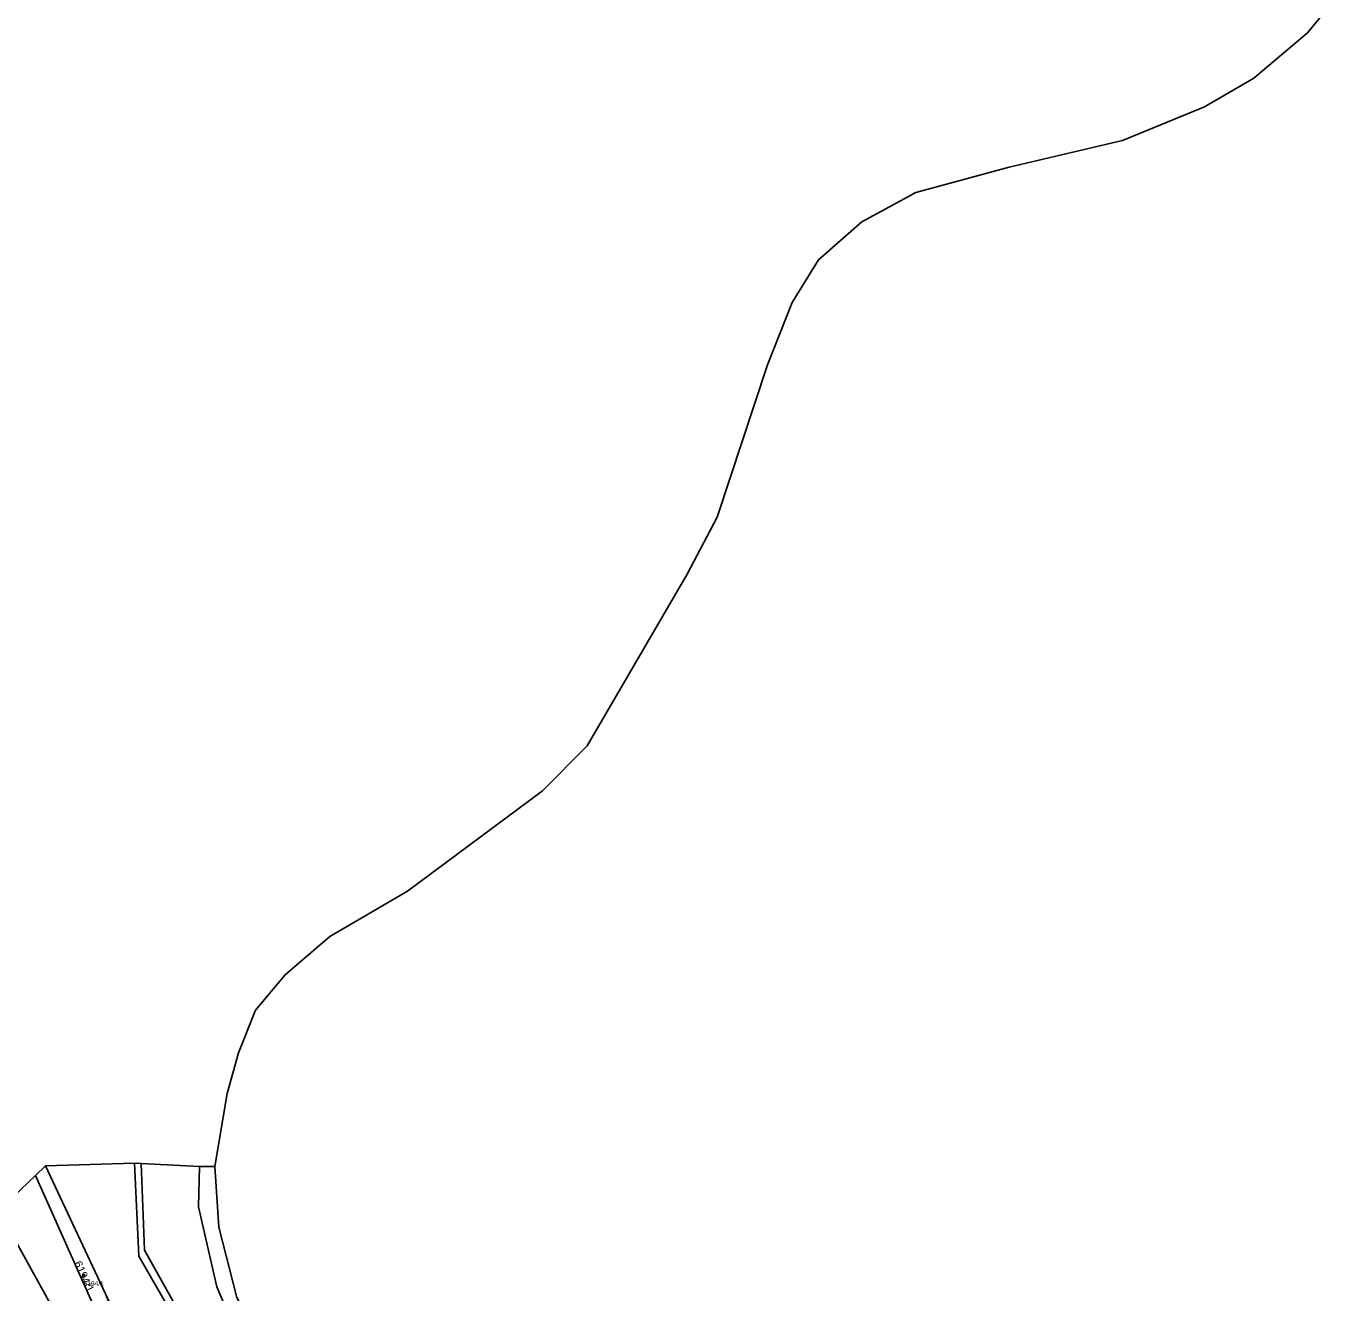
# Model space of a CAD drawing. Extents: x -754150 to -749824, y -1058608 to -1053956.
# Drawn here: x -753501.7 to -753222.7, y -1055960.5 to -1055691.3 of the extents above; entities that cross this region are included whole.
import ezdxf

# ---------------------------------------------------------------- set-up
doc = ezdxf.new("R2010")
doc.units = 0
for name, color, linetype in [('Vrstva 1', 7, 'Continuous'), ('Vrstva 2', 7, 'Continuous'), ('Vrstva 50', 7, 'Continuous'), ('Vrstva 51', 7, 'Continuous'), ('Vrstva 53', 7, 'Continuous')]:
    doc.layers.add(name, color=color, linetype=linetype)

msp = doc.modelspace()

# ---------------------------------------------------------------- linework, layer by layer
at = {"layer": 'Vrstva 1'}
for p, q in [((-753354.9, -1055795.67), (-753344.24, -1055763.29)), ((-753361.32, -1055807.74), (-753354.9, -1055795.67)), ((-753382.57, -1055844.21), (-753361.32, -1055807.74)), ((-753392.04, -1055853.78), (-753382.57, -1055844.21)), ((-753420.74, -1055875.1), (-753392.04, -1055853.78)), ((-753497.62, -1055933.49), (-753478.72, -1055932.93)), ((-753478.72, -1055932.93), (-753477.31, -1055932.99)), ((-753477.31, -1055932.99), (-753464.9, -1055933.61)), ((-753507.59, -1055943.01), (-753499.79, -1055935.57)), ((-753499.79, -1055935.57), (-753497.62, -1055933.49)), ((-753497.62, -1055933.49), (-753484.98, -1055960.55)), ((-753464.9, -1055933.61), (-753461.69, -1055933.61))]:
    msp.add_line(p, q, dxfattribs=at)
for points in [[(-753344.24, -1055763.29), (-753339.02, -1055750.02), (-753333.4, -1055740.97), (-753324.16, -1055732.93), (-753312.73, -1055726.7), (-753292.87, -1055721.27), (-753268.8, -1055715.65), (-753251.37, -1055708.45), (-753240.91, -1055702.38), (-753229.47, -1055692.73), (-753222.65, -1055684.29)], [(-753461.69, -1055933.61), (-753459.07, -1055918.12), (-753456.6, -1055909.51), (-753453.01, -1055900.39), (-753446.73, -1055892.88), (-753437.24, -1055884.79), (-753420.74, -1055875.1)], [(-753478.72, -1055932.93), (-753477.78, -1055952.7), (-753457.37, -1055988.27), (-753443.25, -1056005.88), (-753396.93, -1056060.7), (-753389.99, -1056071.74)], [(-753477.31, -1055932.99), (-753476.58, -1055951.4), (-753456.25, -1055987.76), (-753395.56, -1056059.9)], [(-753499.79, -1055935.57), (-753484, -1055970.96), (-753469.65, -1055999.21), (-753467.46, -1056002.4)], [(-753395.56, -1056059.9), (-753398.84, -1056047.64), (-753402.33, -1056029.73), (-753405.6, -1056019.5), (-753411.73, -1056009.98), (-753445.5, -1055990.4), (-753448.91, -1055981.52), (-753456.09, -1055971.4), (-753461.26, -1055959.21), (-753465.12, -1055942.18), (-753464.9, -1055933.61)], [(-753383.67, -1056071.64), (-753386.95, -1056065.57), (-753392.18, -1056056.2), (-753395.05, -1056046.53), (-753397.11, -1056035.53), (-753400.64, -1056019.78), (-753404.8, -1056009.8), (-753409.93, -1056004.7), (-753438.79, -1055985.36), (-753444.11, -1055980.37), (-753446.71, -1055977.48), (-753451.33, -1055972.24), (-753456.98, -1055961.5), (-753460.8, -1055946.49), (-753461.69, -1055933.61)], [(-753409.35, -1056084.33), (-753420.75, -1056076.85), (-753425.9, -1056071.59), (-753436.92, -1056060.89), (-753447.55, -1056046.37), (-753463.02, -1056023), (-753476.31, -1056001.98), (-753490.2, -1055974.43), (-753507.59, -1055943.01)]]:
    msp.add_lwpolyline(points, dxfattribs=at)
at = {"layer": 'Vrstva 50'}
msp.add_circle((-753489.5, -1055956.84), 0.25, dxfattribs=at)
at = {"layer": 'Vrstva 51'}
for points in [[(-753222.65, -1055684.29), (-753229.47, -1055692.73), (-753240.91, -1055702.38), (-753251.37, -1055708.45), (-753268.8, -1055715.65), (-753292.87, -1055721.27), (-753312.73, -1055726.7), (-753324.16, -1055732.93), (-753333.4, -1055740.97), (-753339.02, -1055750.02), (-753344.24, -1055763.29), (-753354.9, -1055795.67), (-753361.32, -1055807.74), (-753382.57, -1055844.21), (-753392.04, -1055853.78), (-753420.74, -1055875.1), (-753437.24, -1055884.79), (-753446.73, -1055892.88), (-753453.01, -1055900.39), (-753456.6, -1055909.51), (-753459.07, -1055918.12), (-753461.69, -1055933.61), (-753460.8, -1055946.49), (-753456.98, -1055961.5)], [(-753456.98, -1055961.5), (-753460.8, -1055946.49), (-753461.69, -1055933.61), (-753464.9, -1055933.61), (-753465.12, -1055942.18), (-753461.26, -1055959.21), (-753456.09, -1055971.4)], [(-753490.2, -1055974.43), (-753507.59, -1055943.01)]]:
    msp.add_lwpolyline(points, dxfattribs=at)
for points in [[(-753395.97, -1056070.88), (-753394.84, -1056072.35), (-753389.99, -1056071.74), (-753396.93, -1056060.7), (-753443.25, -1056005.88), (-753457.37, -1055988.27), (-753477.78, -1055952.7), (-753478.72, -1055932.93), (-753497.62, -1055933.49), (-753484.98, -1055960.55), (-753472.49, -1055987.65), (-753459.97, -1056005.11), (-753449.18, -1056016.59), (-753434.77, -1056029.57), (-753422.76, -1056039.58), (-753414.4, -1056049.36), (-753405.46, -1056059.5)], [(-753396.93, -1056060.7), (-753389.99, -1056071.74), (-753388.26, -1056071.48), (-753395.56, -1056059.9), (-753456.25, -1055987.76), (-753476.58, -1055951.4), (-753477.31, -1055932.99), (-753478.72, -1055932.93), (-753477.78, -1055952.7), (-753457.37, -1055988.27), (-753443.25, -1056005.88)], [(-753395.56, -1056059.9), (-753398.84, -1056047.64), (-753402.33, -1056029.73), (-753405.6, -1056019.5), (-753411.73, -1056009.98), (-753445.5, -1055990.4), (-753448.91, -1055981.52), (-753456.09, -1055971.4), (-753461.26, -1055959.21), (-753465.12, -1055942.18), (-753464.9, -1055933.61), (-753477.31, -1055932.99), (-753476.58, -1055951.4), (-753456.25, -1055987.76)], [(-753409.35, -1056084.33), (-753398.14, -1056082.71), (-753403.01, -1056081.24), (-753416.8, -1056070.96), (-753421.38, -1056067.21), (-753430.8, -1056057.05), (-753442.03, -1056042.55), (-753456.87, -1056019.99), (-753467.46, -1056002.4), (-753469.65, -1055999.21), (-753484, -1055970.96), (-753499.79, -1055935.57), (-753507.59, -1055943.01), (-753490.2, -1055974.43), (-753476.31, -1056001.98), (-753463.02, -1056023), (-753447.55, -1056046.37), (-753436.92, -1056060.89), (-753425.9, -1056071.59), (-753420.75, -1056076.85)], [(-753499.79, -1055935.57), (-753484, -1055970.96), (-753469.65, -1055999.21), (-753467.46, -1056002.4), (-753484.98, -1055960.55), (-753497.62, -1055933.49)]]:
    msp.add_lwpolyline(points, close=True, dxfattribs=at)
at = {"layer": 'Vrstva 53'}
msp.add_lwpolyline([(-753222.65, -1055684.29), (-753229.47, -1055692.73), (-753240.91, -1055702.38), (-753251.37, -1055708.45), (-753268.8, -1055715.65), (-753292.87, -1055721.27), (-753312.73, -1055726.7), (-753324.16, -1055732.93), (-753333.4, -1055740.97), (-753339.02, -1055750.02), (-753344.24, -1055763.29), (-753354.9, -1055795.67), (-753361.32, -1055807.74), (-753382.57, -1055844.21), (-753392.04, -1055853.78), (-753420.74, -1055875.1), (-753437.24, -1055884.79), (-753446.73, -1055892.88), (-753453.01, -1055900.39), (-753456.6, -1055909.51), (-753459.07, -1055918.12), (-753461.69, -1055933.61), (-753464.9, -1055933.61), (-753477.31, -1055932.99), (-753478.72, -1055932.93), (-753497.62, -1055933.49), (-753499.79, -1055935.57), (-753507.59, -1055943.01)], dxfattribs=at)

# ---------------------------------------------------------------- texts
at = {"layer": 'Vrstva 2'}
msp.add_text('6194/1', height=1.7, rotation=294, dxfattribs=at).set_placement((-753491.62, -1055954.17))
at = {"layer": 'Vrstva 50'}
msp.add_text('6194/1', height=1, dxfattribs=at).set_placement((-753489.5, -1055959))

doc.saveas('drawing.dxf')
